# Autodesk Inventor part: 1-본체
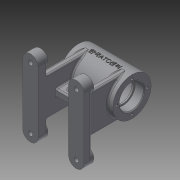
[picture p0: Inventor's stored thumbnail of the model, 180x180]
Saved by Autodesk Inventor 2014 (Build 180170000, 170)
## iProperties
Created: 2015-11
Part Number: 1-본체
Material: Generic
Document SubType Name: Modeling
Designer: test_26
Density: 1 g/cm^3
Appearance: Default
Author: test_26
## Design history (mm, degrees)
sketch "스케치1"
  geometry: L1 (35, 0)-(-35, 0); L2 (-35, 0)-(-35, 25); L3 (-35, 25)-(35, 25); L4 (35, 25)-(35, 0); L5 (-35, 16)-(-23, 16); L6 (-23, 16)-(-23, 14); L7 (-23, 14)-(-21, 14); L8 (-21, 14)-(-21, 21); L9 (-21, 21)-(21, 21); L10 (21, 21)-(21, 14); L11 (21, 14)-(23, 14); L12 (23, 14)-(23, 16); L13 (23, 16)-(35, 16); 2 further points
  constraints: 26 end point, 8 parallel, 4 perpendicular, 2 point on line, 1 coincident, 1 horizontal, 1 midpoint
  dimensions: "d0" = 50 diameter of L3 L1; "d1" = 28 diameter of L7 L1; "d2" = 32 diameter of L5 L1; "d3" = 32 diameter of L13 L1; "d4" = 42 diameter of L9 L1; "d5" = 28 diameter of L11 L1; "d6" = 12 distance of L5.start L5.end; "d7" = 70 distance between parallel lines of L4 L2; "d8" = 42 distance of L8.end L9.end; "d9" = 12 distance of L12.end L13.end; "d10" = 2 distance of L6.end L7.end
revolve "회전1" sketch "스케치1" stored, may be unused: angle "d11" = 90 deg
node "작업 평면1"
sketch "스케치2"
  geometry: L1 (-30, -40)-(-30, 40); L2 (-20, -40)-(-20, 40); L3 (-40, 40)-(-40, -40); L4 (30, -40)-(30, 40); L5 (20, -40)-(20, 40); L6 (40, 40)-(40, -40); C1 r 10 at (-30, 40); C2 r 10 at (30, 40); C3 r 10 at (-30, -40); C4 r 10 at (30, -40); A1 r 10 centre (-30, -40) between (-40, -40) and (-20, -40); A2 r 10 centre (-30, 40) between (-20, 40) and (-40, 40); A3 r 10 centre (30, -40) between (20, -40) and (40, -40); A4 r 10 centre (30, 40) between (40, 40) and (20, 40); 3 further points
  constraints: 16 end point, 8 centre point, 8 point on circle, 8 tangent, 4 coincident, 3 parallel, 2 concentric, 2 horizontal alignment, 2 midpoint, 1 vertical
  dimensions: "d13" = 20 distance between parallel lines of L2 L3; "d14" = 80 distance of L1.start L1.end; "d15" = 80 distance of L4.start L4.end; "d16" = 80 distance between parallel lines of L6 L3; "d18" = 40 distance from line of point (0, 0) L3; "d19" = 20 distance between parallel lines of L6 L5; "d20" = 20 diameter of C1; "d21" = 20 diameter of C2
extrude "돌출1" join sketch "스케치2" distance "d22" = 10; taper "d23" = 0 deg
extrude "돌출2" join sketch "스케치2" distance "d24" = 13; taper "d25" = 0 deg
sketch "스케치3"
  geometry: L1 (-20, -40)-(-20, 40) reference; L2 (-20, 25)-(-28, 25); L3 (-28, 25)-(-28, -25); L4 (-28, -25)-(-20, -25); L5 (-20, -25)-(-20, 25); L6 (20, 25)-(28, 25); L7 (28, 25)-(28, -25); L8 (28, -25)-(20, -25); L9 (20, -25)-(20, 25); L10 (20, 40)-(20, -40) reference; 3 further points
  constraints: 16 end point, 4 parallel, 2 horizontal, 2 horizontal alignment, 2 midpoint, 2 perpendicular, 1 collinear, 1 point on line
  dimensions: "d26" = 50 distance between parallel lines of L4 L2; "d27" = 50 distance between parallel lines of L8 L6; "d28" = 8 distance between parallel lines of L1 L3; "d30" = 8 distance between parallel lines of L7 L9
extrude "돌출3" join sketch "스케치3" stored distance "d31" = 13; taper "d32" = 0 deg
node "작업 평면2"
sketch "스케치4"
  geometry: L1 (20, -4)-(-20, -4); L2 (-20, -4)-(-20, 4); L3 (-20, 4)-(20, 4); L4 (20, 4)-(20, -4); L5 (20, -4)-(-20, 4); L6 (-20, -4)-(20, 4); L7 (-20, -40)-(-20, 40) reference; L8 (20, -40)-(20, 40) reference; 1 further point
  constraints: 12 end point, 2 midpoint, 2 parallel, 1 collinear, 1 horizontal, 1 perpendicular
  dimensions: "d34" = 8 distance between parallel lines of L1 L3
extrude "돌출4" join sketch "스케치4" stored distance "d35" = 13; taper "d36" = 0 deg
sketch "스케치5"
  geometry: L1 (0, 20.322)-(40, 20.322) reference; L2 (28, 10)-(12, 10); L3 (28, 13.5)-(12, 13.5); L4 (12, 6.5)-(28, 6.5); L5 (40, -23)-(60, -23) reference; A1 r 3.5 centre (28, 10) between (28, 6.5) and (28, 13.5); A2 r 3.5 centre (12, 10) between (12, 13.5) and (12, 6.5); 2 further points
  constraints: 8 end point, 4 point on circle, 4 tangent, 2 centre point, 2 parallel, 1 midpoint, 1 vertical alignment
  dimensions: "d37" = 33 distance from line of L5 point (20, 10); "d38" = 23 dimension on A1 A2; "d39" = 3.5 radius of A2
extrude "돌출5" cut sketch "스케치5" stored distance "d40" = 13; taper "d41" = 0 deg
sketch "스케치6"
  geometry: C1 r 10 at (0, 0) reference; C2 r 6 at (0, 0); 1 further point
  constraints: 1 centre point, 1 coincident
  dimensions: "d42" = 12 diameter of C2
extrude "돌출6" cut sketch "스케치6" distance "d43" = 4; taper "d44" = 0 deg
sketch "스케치7"
  geometry: C1 r 3 at (-30, -40); A1 r 10 centre (-30, -40) between (-40, -40) and (-20, -40) reference; 1 further point
  constraints: 1 centre point, 1 coincident
  dimensions: "d45" = 6 diameter of C1
extrude "돌출7" cut sketch "스케치7" stored distance "d46" = 4; taper "d47" = 0 deg
sketch "스케치9"
  geometry: C1 r 16 at (0, 0) reference; 1 further point
  constraints: 1 vertical alignment
  dimensions: "d48" = 20 distance of point (0, 20) C1.centre
hole "구멍1" sketch "스케치9" at (0, 20) diameter "d49" = 3.242; stored, may be unused: countersink angle "d53" = 90 deg, drill point angle "d55" = 118 deg; dims "d50" = 8, "d51" = 4, "d52" = 2, "d54" = 10
node "작업 평면3"
sketch "스케치10"
  geometry: C1 r 5 at (0, 0); 1 further point
  constraints: 1 centre point, 1 coincident
  dimensions: "d60" = 10 diameter of C1
extrude "돌출8" join sketch "스케치10" stored distance "d61" = 4; taper "d62" = 0 deg
sketch "스케치11"
  geometry: C1 r 5 at (0, 0) reference; 1 further point
  constraints: 1 coincident
hole "구멍2" sketch "스케치11" at (0, 0) diameter "d63" = 5.188; stored, may be unused: countersink angle "d67" = 90 deg, drill point angle "d69" = 118 deg; dims "d64" = 8, "d65" = 4, "d66" = 2, "d68" = 10
sketch "스케치12"
  geometry: L1 (0, 0)-(-24.249, -14); L2 (0, 0)-(-31.998, 0)
  constraints: 4 end point, 1 horizontal
  dimensions: "d70" = 30 deg angle of L2 L1; "d71" = 28 distance of L1.start L1.end
node "작업 평면4"
sketch "스케치13"
  geometry: C1 r 6 at (0, 0); 1 further point
  constraints: 1 centre point, 1 coincident
  dimensions: "d72" = 12 diameter of C1
extrude "돌출9" join sketch "스케치13" stored distance "d73" = 4; taper "d74" = 0 deg
sketch "스케치14"
  geometry: C1 r 6 at (0, 0) reference; 1 further point
  constraints: 1 coincident
hole "구멍3" sketch "스케치14" at (0, 0) diameter "d75" = 5.188; stored, may be unused: countersink angle "d79" = 90 deg, drill point angle "d81" = 118 deg; dims "d76" = 10, "d77" = 4, "d78" = 2, "d80" = 10
node "작업 평면5"
sketch "스케치16"
  geometry: L1 (-35, 25)-(35, 25) reference; L2 (35, -25)-(35, 25) reference; 2 further points
  constraints: 1 other
  dimensions: "d83" = 25 distance from line of L1 point (0, 0); "d84" = 35 distance from line of L2 point (0, 0)
feature "엠보싱1" sketch "스케치16" dims "d0" = 50, "d1" = 28, "d2" = 32, "d3" = 32, "d4" = 42, "d5" = 28, "d6" = 12, "d7" = 70, "d8" = 42, "d9" = 12, "d10" = 2, "d13" = 20, "d14" = 80, "d15" = 80, "d16" = 80, "d18" = 40, "d19" = 20, "d20" = 20, "d21" = 20, "d85" = 0.5, "d86" = 0
fillet "모깎기1" dims "d87" = 0.3
fillet "모깎기2" dims "d88" = 3
fillet "모깎기3" dims "d92" = 2
fillet "모깎기4" dims "d93" = 2
fillet "모깎기5" dims "d94" = 2
fillet "모깎기6" dims "d95" = 2
chamfer "모따기2" distance "d96" = 1; stored, may be unused: second distance "d97" = 2, angle "d98" = 45 deg
fillet "모깎기7" dims "d99" = 0.3
node "솔리드1"
mirror "대칭1"
mirror "대칭2"
pattern_circular "원형 패턴1" dims angle "d57" = 360 deg
mirror "대칭3"
other parameters: "d12" = -68, "d33" = -45, "d59" = 28, "d82" = 25.5
